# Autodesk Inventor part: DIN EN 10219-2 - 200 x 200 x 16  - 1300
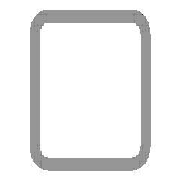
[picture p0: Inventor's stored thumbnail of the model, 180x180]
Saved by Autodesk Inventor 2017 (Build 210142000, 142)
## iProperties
Created: 2017-11
Part Number: DIN EN 10219-2 - 200 x 200 x 16  - 1300
Material: Steel, Mild
Description: Cold formed welded structural hollow sections of non-alloy and fine grain structural steel
Document SubType Name: Modeling
Standard: DIN
Designer: iusti
Standard Revision: 2006-07
Standards Organization: DIN
Language: en-US
Size Designation: 200 x 200 x 16
Categories: <MemberInstance><Categories><Category DisplayName="Structural Shapes" InternalName="089c4875-fa83-4c05-b084-43b9cc11f5ed" Mnemonic="GRDR"><CategoryParameter Dis
Stock Number: 200 x 200 x 16
Mass: 108961 g
Surface Area: 17564.1 cm^2
Volume: 13880.4 cm^3
Density: 7.85 g/cm^3
Appearance: Semi-Polished
_CCFamilyMember: 103
_CCFamilyDisplayName: DIN EN 10219-2 (Square Hollow Section - Cold Formed) - Cold formed welded structural hollow sections of non-alloy and fine grain structural steel
_FrameMemberDoc: Frame Member File
_Version: 15.0.0
_GetPNFromCC: 1
G_L: 1300.000 mm
G_W: 200.000 mm
G_H: 200.000 mm
+746405E1-1F2D-47B5-93D3-CB58C56AE875+CUTDETAIL1: Cut
+F08F13D1-F71F-41A8-894A-BF7039D3AEA5+CUTDETAIL2: Cut
+B83B782A-F5FC-4E0E-926C-3EFD3F60499E+CUTDETAIL3: Cut
IsCustomPart: 1
Author: iusti
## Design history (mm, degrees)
node "Start plane"
node "End plane"
sketch "Sketch"
  geometry: L1 (-100, -52)-(-100, 52); L2 (-52, 100)-(52, 100); L3 (100, 52)-(100, -52); L4 (52, -100)-(-52, -100); L5 (-52, 84)-(52, 84); L6 (84, 52)-(84, -52); L7 (52, -84)-(-52, -84); L8 (-84, -52)-(-84, 52); L9 (0, 153.918)-(0, -153.918) reference; L10 (-153.918, 0)-(153.918, 0) reference; A1 r 48 centre (-52, -52) between (-100, -52) and (-52, -100); A2 r 48 centre (-52, 52) between (-52, 100) and (-100, 52); A3 r 48 centre (52, 52) between (100, 52) and (52, 100); A4 r 48 centre (52, -52) between (52, -100) and (100, -52); A5 r 32 centre (-52, 52) between (-52, 84) and (-84, 52); A6 r 32 centre (52, 52) between (84, 52) and (52, 84); A7 r 32 centre (52, -52) between (52, -84) and (84, -52); A8 r 32 centre (-52, -52) between (-84, -52) and (-52, -84)
  constraints: 16 end point, 16 point on circle, 8 centre point, 8 tangent, 4 parallel, 3 equal radius, 2 perpendicular, 7 other
  dimensions: "d7" = 48 radius of A1 (= G_IR); "d10" = 200 distance between parallel lines of L2 L4 (= G_H); "d11" = 200 distance between parallel lines of L1 L3 (= G_W); "d12" = 16 distance between parallel lines of L3 L6 (= G_T); "d15" = 100 distance between parallel lines of L2 L10 (= 0.5 x d10); "d16" = 100 distance between parallel lines of L9 L3 (= 0.5 x d11)
extrude "Body" new body sketch "Sketch" stored distance "d3" = 1300 (= G_L); taper "d4" = 0 deg
node "Driven Length"
  sketch "Sketch3"
    geometry: L1 (0, 0)-(10, 0) reference
    constraints: 2 end point, 1 horizontal
  workplane "Work Plane3"
  sketch "Sketch4"
    geometry: L1 (-2, 100)-(12, 100) reference; L2 (-2, 1400)-(12, 1400) reference
    dimensions: "d18" = 1300 distance between parallel lines of L1 L2 (derived)
workplane "Work Plane4"
split "Split1"
workplane "Work Plane5"
split "Split2"
workplane "Work Plane6"
split "Split3"
body "Solid1"
other parameters: "G_W" = 200 [user parameter; used in 1 equation term], "G_H" = 200 [user parameter; used in 1 equation term], "G_T" = 16 [user parameter; used in 1 equation term], "G_IR" = 48 [user parameter; used in 1 equation term], "G_L" = 1300 (= d18) [user parameter; used in 1 equation term], "d17" = 90 deg
